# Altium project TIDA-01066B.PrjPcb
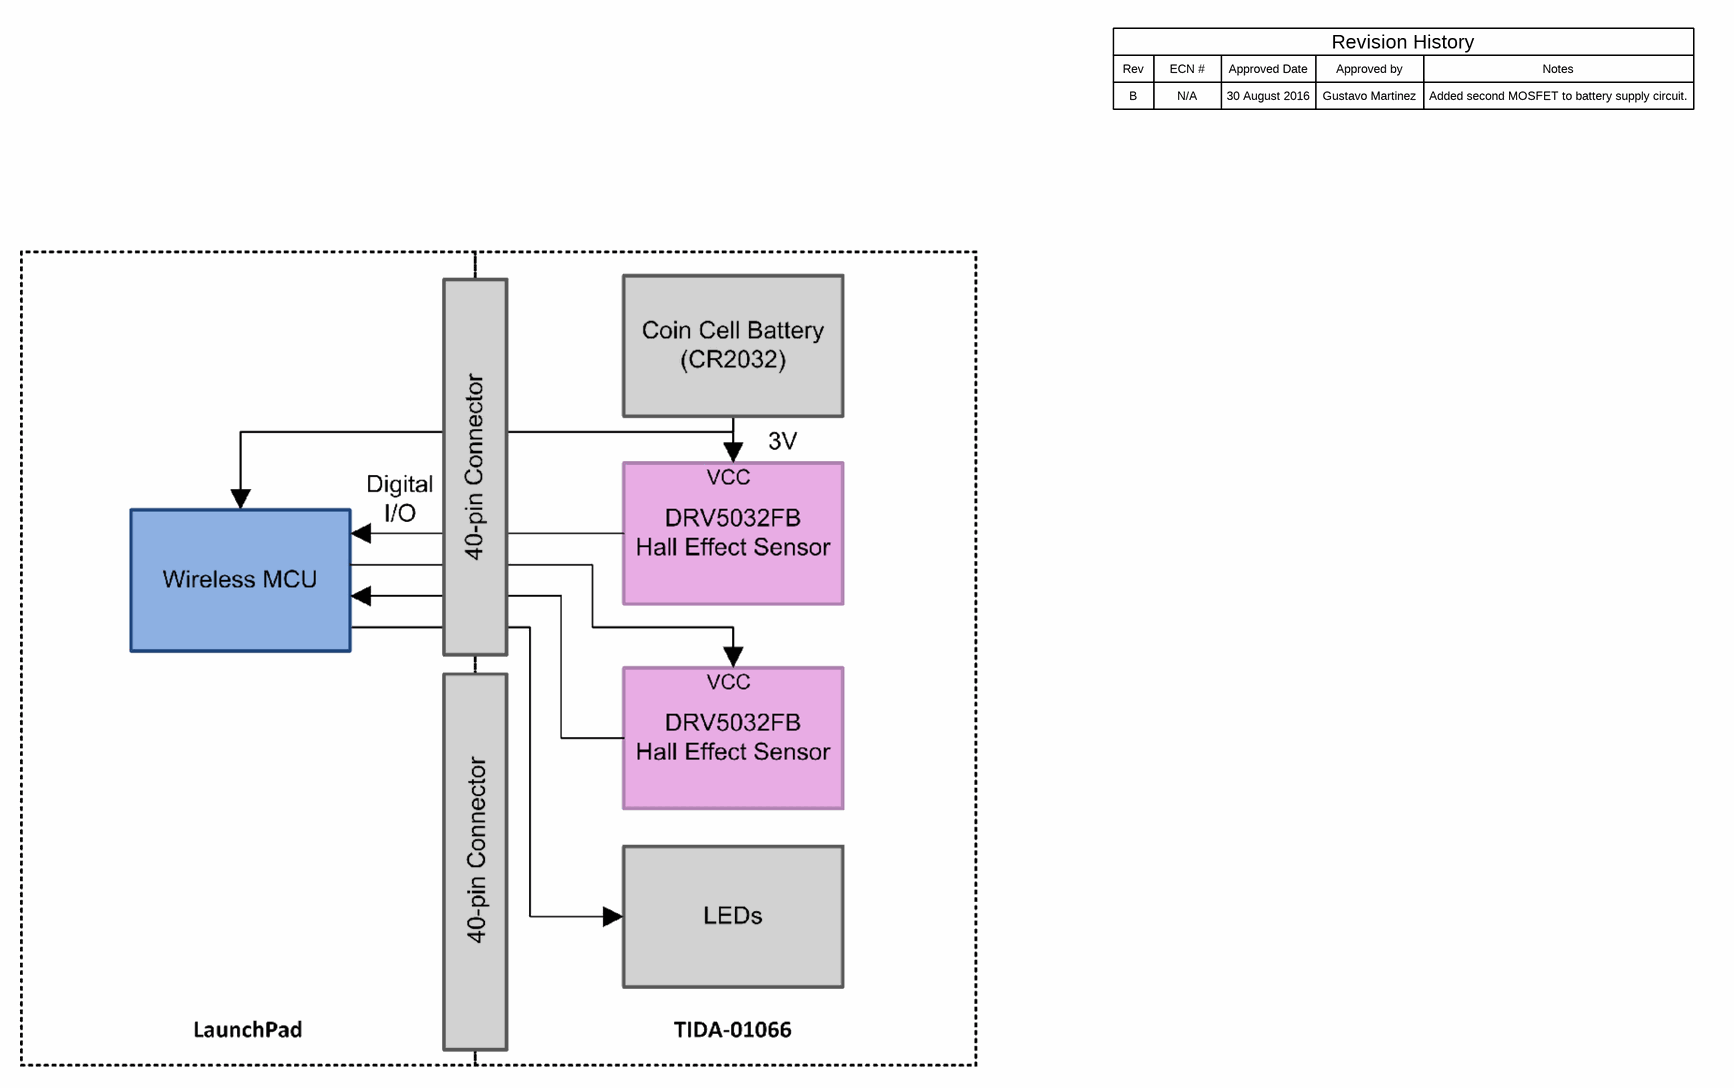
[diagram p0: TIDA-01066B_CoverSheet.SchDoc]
CopyrightYear: 2016; PCB_Layout: Krypton Solutions/RS; PCB_Rev: B; PRJ_Customer: Public Release; PRJ_Engineer: Gustavo Martinez; PRJ_Number: TIDA-01066; PRJ_Title: Low Power Window Contact Switch with Sub-1GHz; SCH_Rev: B; TechSupport: http://www.ti.com/support; TID: TIDA-01066
3 sheets, 44 parts. Net scope: global (net labels, ports and power ports of the same name join across sheets).
Board file: TIDA-01066B_PCB.PcbDoc
Sheets:
  TIDA-01066B_CoverSheet.SchDoc
  TIDA-01066B_Hall_Effect_Sensor.SchDoc
  TIDA-01066B_EVM_Hardware.SchDoc

## Sheet TIDA-01066B_CoverSheet.SchDoc: Cover Sheet
size 431 x 279 mm; Date: Not shown in title block; ApprovedBy: Not shown in title block; CheckedBy: Not shown in title block; Author: Not shown in title block; CompanyName: Not shown in title block; Engineer: Not shown in title block; Organization: Not shown in title block; Address1: Not shown in title block; Address2: Not shown in title block; Address3: Not shown in title block; Address4: Not shown in title block; DocumentNumber: 1; Revision: Use project parameter SCH_Rev; SheetNumber: 1; SheetTotal: 3; PageSetup: Record=PageOptions¦CenterHorizontal=True¦CenterVertical=True¦PrintScale=1.00¦XCorrection=1.00¦YCorrection=1.00¦PrintKind=0¦BorderSize=5000000¦LeftOffset=0¦BottomOffset=0¦Orientation=2¦PaperLength=1000¦PaperWidth=1000¦Scale=100¦PaperSource=15¦PrintQuality=600¦MediaType=1¦DitherType=10¦PaperKind=Letter¦PrintScaleMode=1

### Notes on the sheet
- Rev
- B
- ECN #
- N/A
- Approved Date
- 30 August 2016
- Approved by
- Gustavo Martinez
- Revision History
- Notes
- Added second MOSFET to battery supply circuit.

## Sheet TIDA-01066B_Hall_Effect_Sensor.SchDoc: Hall Effect Sensors
size 431 x 279 mm; Date: Not shown in title block; ApprovedBy: Not shown in title block; CheckedBy: Not shown in title block; Author: Not shown in title block; CompanyName: Not shown in title block; Engineer: Not shown in title block; Organization: Not shown in title block; Address1: Not shown in title block; Address2: Not shown in title block; Address3: Not shown in title block; Address4: Not shown in title block; DocumentNumber: 1; Revision: Use project parameter SCH_Rev; SheetNumber: 2; SheetTotal: 3; PageSetup: Record=PageOptions¦CenterHorizontal=True¦CenterVertical=True¦PrintScale=1.00¦XCorrection=1.00¦YCorrection=1.00¦PrintKind=0¦BorderSize=5000000¦LeftOffset=0¦BottomOffset=0¦Orientation=2¦PaperLength=1000¦PaperWidth=1000¦Scale=100¦PaperSource=15¦PrintQuality=600¦MediaType=1¦DitherType=10¦PaperKind=Letter¦PrintScaleMode=1
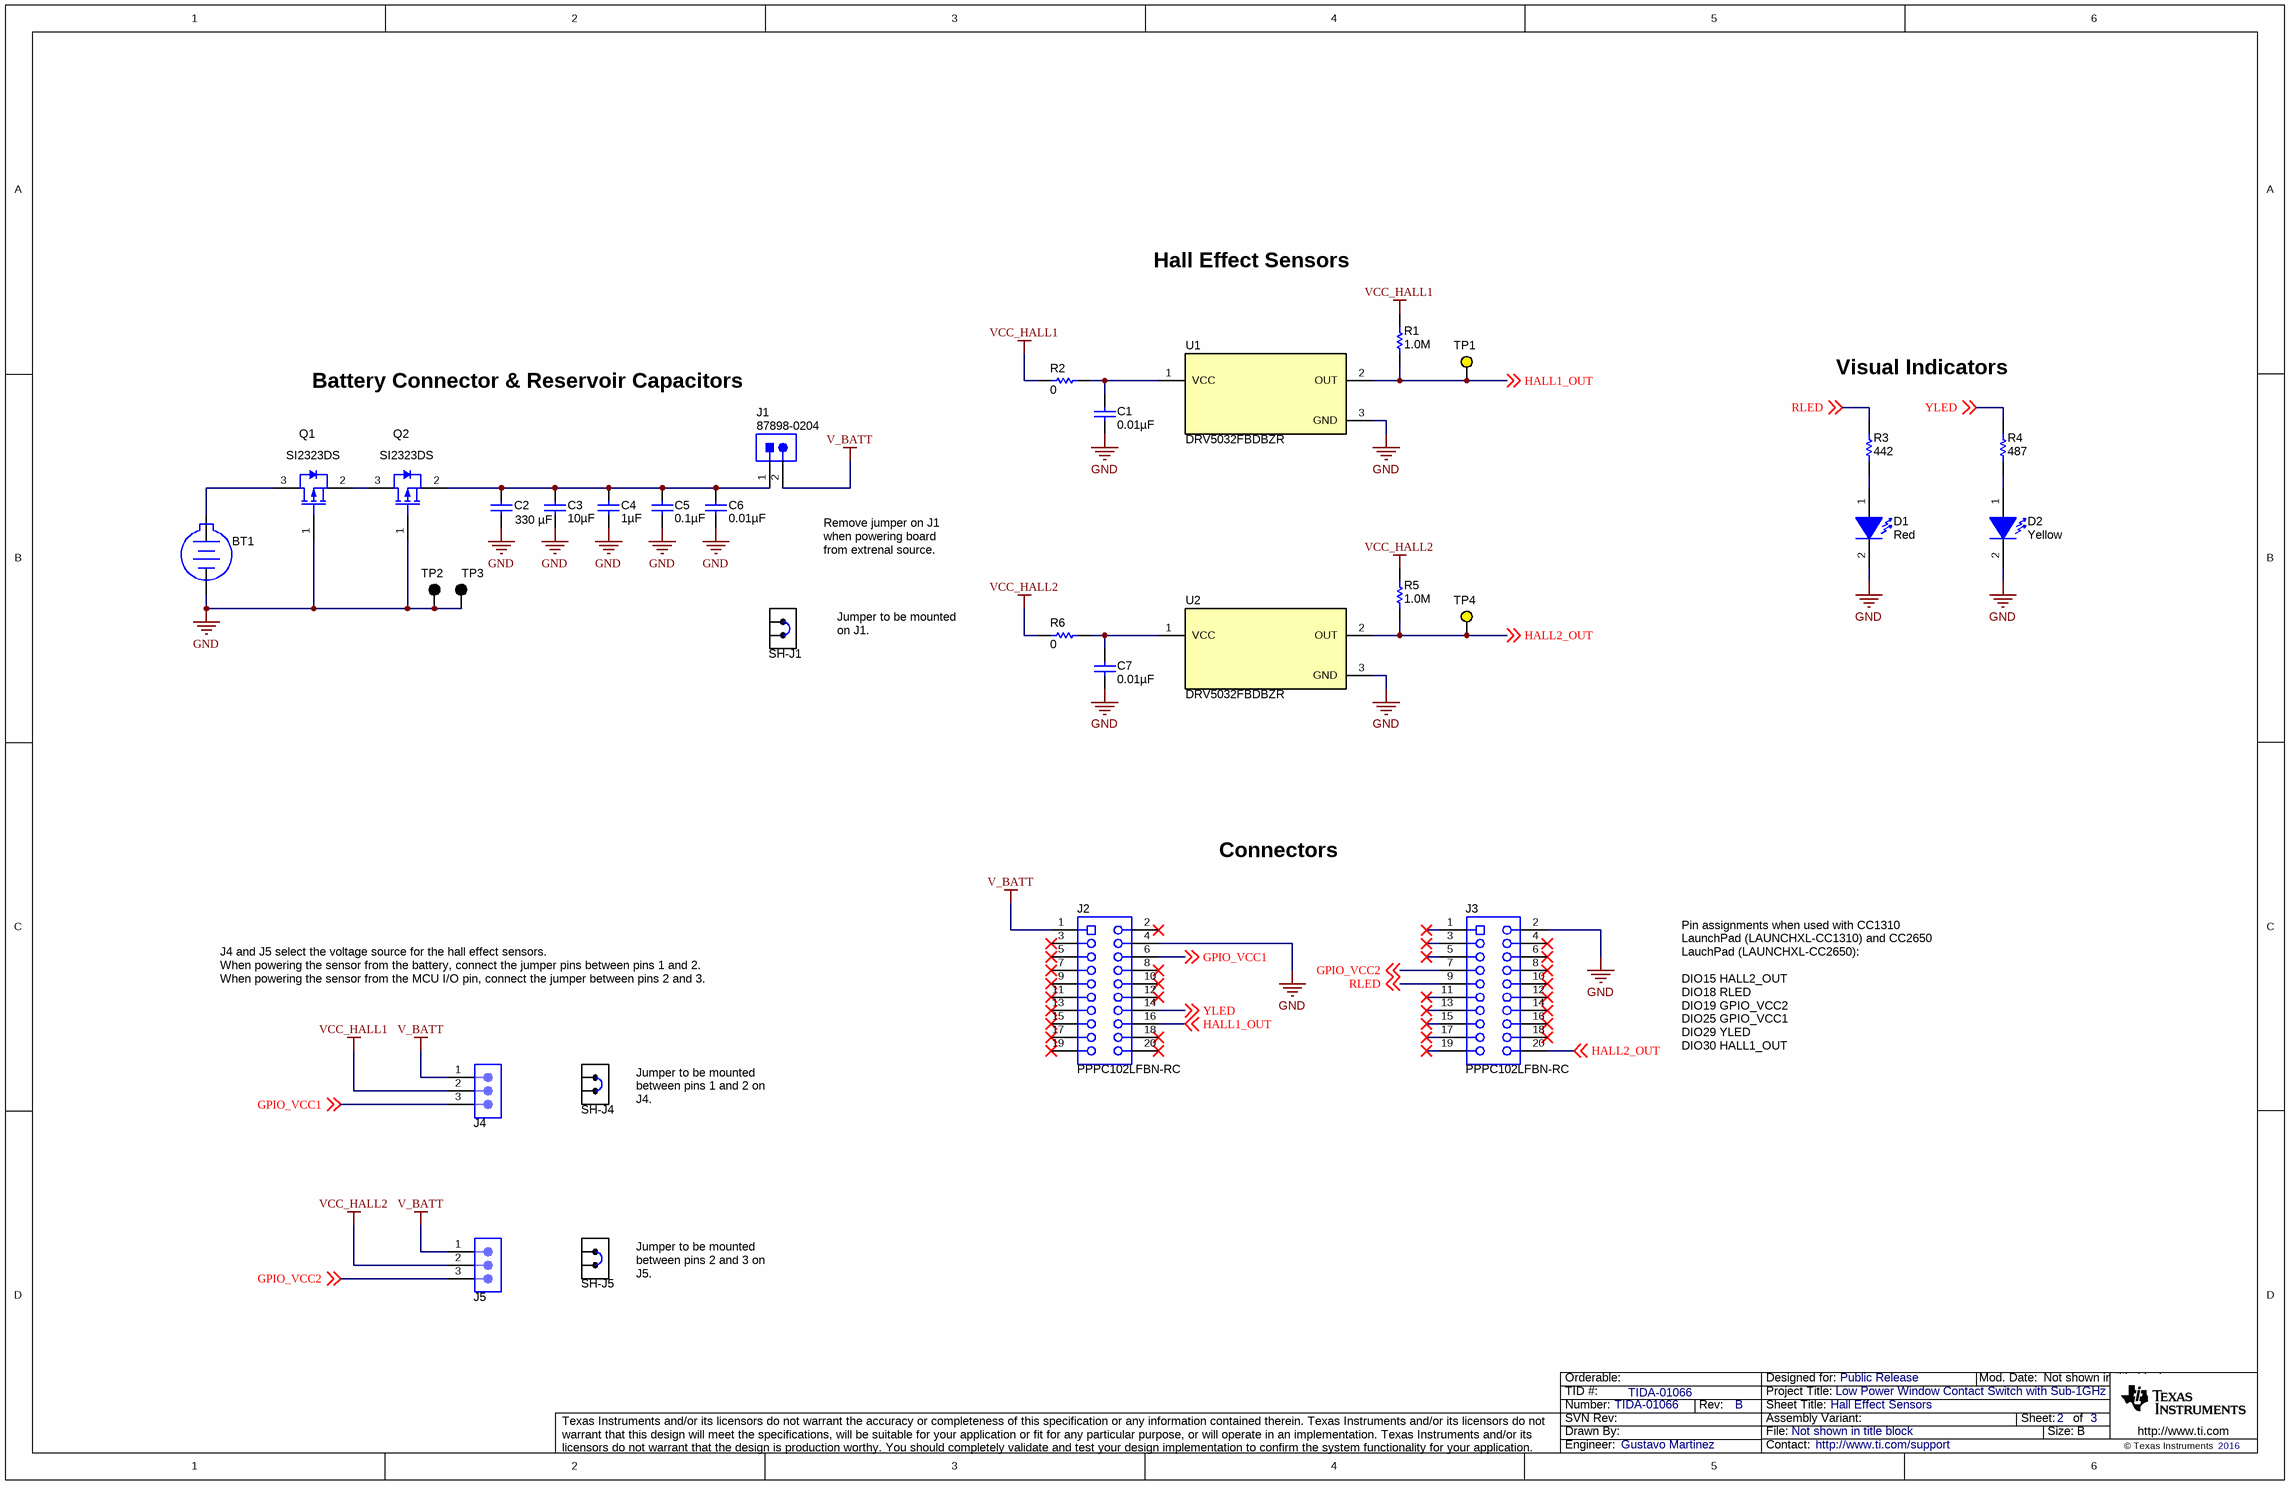
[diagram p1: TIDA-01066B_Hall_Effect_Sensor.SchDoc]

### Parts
BT1  BS-7  [BAT_BS-7]  (value not drawn)
C1  ValueDisplayed: 0.01µF  [0402]  (hidden comment: GRM155R71C103KA01D)
C2  ValueDisplayed: 330 µF  [1210]  (hidden comment: GRM32ER60G337ME05L)
C3  ValueDisplayed: 10µF  [0603]  (hidden comment: C1608X5R0J106M)
C4  ValueDisplayed: 1µF  [0603]  (hidden comment: C1608X7R1C105K)
C5  ValueDisplayed: 0.1µF  [0402]  (hidden comment: C1005X7R1H104K050BB)
C6  ValueDisplayed: 0.01µF  [0402]  (hidden comment: C1005X7R1C103K050BA)
C7  ValueDisplayed: 0.01µF  [0402]  (hidden comment: GRM155R71C103KA01D)
D1  value Red  [LS L29K_Red]  (hidden comment: LS L29K-G1J2-1-Z)
D2  value Yellow  [LY L29K_Yellow]  (hidden comment: LY L29K-H1K2-26-Z)
J1  87898-0204  [Molex_87898-0204]
J2  PPPC102LFBN-RC  [Sullins_PPPC102LFBN-RC]
J3  PPPC102LFBN-RC  [Sullins_PPPC102LFBN-RC]
J4  PBC03SAAN  [PBC03SAAN]  (value not drawn)
J5  PBC03SAAN  [PBC03SAAN]  (value not drawn)
Q1  SI2323DS  [SOT-23]
Q2  SI2323DS  [SOT-23]
R1  ValueDisplayed: 1.0M  [0805_HV]  (hidden comment: CRCW08051M00JNEA)
R2  ValueDisplayed: 0  [0805_HV]  (hidden comment: CRCW08050000Z0EA)
R3  ValueDisplayed: 442  [0805_HV]  (hidden comment: CRCW0805442RFKEA)
R4  ValueDisplayed: 487  [0805_HV]  (hidden comment: CRCW0805487RFKEA)
R5  ValueDisplayed: 1.0M  [0805_HV]  (hidden comment: CRCW08051M00JNEA)
R6  ValueDisplayed: 0  [0805_HV]  (hidden comment: CRCW08050000Z0EA)
SH-J1  969102-0000-DA  [SNT-100-BK-G]  (value not drawn)
SH-J4  969102-0000-DA  [SNT-100-BK-G]  (value not drawn)
SH-J5  969102-0000-DA  [SNT-100-BK-G]  (value not drawn)
TP1  5004  [Keystone5004]  (value not drawn)
TP2  5011  [Keystone5011]  (value not drawn)
TP3  5011  [Keystone5011]  (value not drawn)
TP4  5004  [Keystone5004]  (value not drawn)
U1  DRV5032FBDBZR  [DBZ0003A_N]
U2  DRV5032FBDBZR  [DBZ0003A_N]

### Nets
GND: BT1.2(-) C1.2 C2.2 C3.2 C4.2 C5.2 C6.2 C7.2 D1.2(K) D2.2(K) J2.4 J3.2 Q1.1(G) Q2.1(G) TP2.1 TP3.1 U1.3(GND) U2.3(GND)
V_BATT: J1.2 J2.1 J4.1 J5.1
VCC_HALL1: J4.2 R1.2 R2.1
VCC_HALL2: J5.2 R5.2 R6.1
GPIO_VCC1: J2.6 J4.3 ; off-sheet GPIO_VCC1
GPIO_VCC2: J3.7 J5.3 ; off-sheet GPIO_VCC2
HALL1_OUT: J2.16 R1.1 TP1.1 U1.2(OUT) ; off-sheet HALL1_OUT
HALL2_OUT: J3.20 R5.1 TP4.1 U2.2(OUT) ; off-sheet HALL2_OUT
RLED: J3.9 R3.2 ; off-sheet RLED
YLED: J2.14 R4.2 ; off-sheet YLED
NetBT1_1: BT1.1(+) Q1.3(D)
NetC1_1: C1.1 R2.2 U1.1(VCC)
NetC2_1: C2.1 C3.1 C4.1 C5.1 C6.1 J1.1 Q2.2(S)
NetC7_1: C7.1 R6.2 U2.1(VCC)
NetD1_1: D1.1(A) R3.1
NetD2_1: D2.1(A) R4.1
NetQ1_2: Q1.2(S) Q2.3(D)

Not connected (* = marked no-connect by the designer): J2 2* 3* 5* 7* 8* 9* 10* 11* 12* 13* 15* 17* 18* 19* 20*; J3 1* 3* 4* 5* 6* 8* 10* 11* 12* 13* 14* 15* 16* 17* 18* 19*

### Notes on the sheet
- Hall Effect Sensors
- Visual Indicators
- Battery Connector & Reservoir Capacitors
- Remove jumper on J1 when powering board from extrenal source.
- Jumper to be mounted on J1.
- Connectors
- J4 and J5 select the voltage source for the hall effect sensors.
  When powering the sensor from the battery, connect the jumper pins between pins 1 and 2.
  When powering the sensor from the MCU I/O pin, connect the jumper between pins 2 and 3.
- Pin assignments when used with CC1310 LaunchPad (LAUNCHXL-CC1310) and CC2650 LauchPad (LAUNCHXL-CC2650):
  DIO15	HALL2_OUT
  DIO18	RLED
  DIO19	GPIO_VCC2
  DIO25	GPIO_VCC1
  DIO29	YLED
  DIO30	HALL1_OUT
- (near SH-J4) Jumper to be mounted between pins 1 and 2 on J4.
- (near SH-J5) Jumper to be mounted between pins 2 and 3 on J5.

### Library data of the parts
BT1 = BS-7: Battery Holder, CR2032, Retainer clip, TH; Manufacturer: Memory Protection Devices; SymbolCreator: a0412235
C1 C7 = GRM155R71C103KA01D: CAP, CERM, 0.01 µF, 16 V, +/- 10%, X7R, 0402; Manufacturer: MuRata; Polarized: N; CompType: Capacitor; Value: 0.01uF; U/M: EA; Cap_F: 0.00000001; Tolerance_%: 10; Value1: Unknown; VDC_V: 16; Value2: 16V; TaMin_C: -55; TaMax_C: 125; SizeArea_mm2: 0.5; SizeAreaWB_mm2: 3; SizeX_mm: 1; SizeZ_mm: 0.6; AEC Category: Q200
C2 = Capacitor: CAP, CERM, 330 µF, 4 V, X5R, +/- 20%, 1210; Manufacturer: Murata; Polarized: N; Value: 330 uF; U/M: EA
C3 = C1608X5R0J106M: CAP, CERM, 10 µF, 6.3 V, +/- 20%, X5R, 0603; Manufacturer: TDK; Polarized: N; CompType: Capacitor; Value: 10uF; U/M: EA; Cap_F: 0.00001; Tolerance_%: 20; ESR_ohm: 0.005; Value1: 0.005 ohm; VDC_V: 6.3; Value2: 6.3V; IRMS_A: 1.9; TaMin_C: -25; TaMax_C: 85; AEC Category: Q200
C4 = C1608X7R1C105K: CAP, CERM, 1 µF, 16 V, +/- 10%, X7R, 0603; Manufacturer: TDK; Polarized: N; CompType: Capacitor; Value: 1uF; U/M: EA; Cap_F: 0.000001; Tolerance_%: 10; ESR_ohm: 0.0057; Value1: 0.0057 ohm; VDC_V: 16; Value2: 16V; TaMin_C: -55; TaMax_C: 125; AEC Category: Q200
C5 = C1005X7R1H104K050BB: CAP, CERM, 0.1 µF, 50 V, +/- 10%, X7R, 0402; Manufacturer: TDK; Polarized: N; CompType: Capacitor; Value: 0.1uF; U/M: EA; Cap_F: 0.0000001; Tolerance_%: 10; Value1: Unknown; VDC_V: 50; Value2: 50V; TaMin_C: -55; TaMax_C: 125; AEC Category: Q200
C6 = C1005X7R1C103K050BA: CAP, CERM, 0.01 µF, 16 V, +/- 10%, X7R, 0402; Manufacturer: TDK; Polarized: N; CompType: Capacitor; Value: 0.01uF; U/M: EA; Cap_F: 0.00000001; Tolerance_%: 10; ESR_ohm: 0.0623; Value1: 0.0623 ohm; VDC_V: 16; Value2: 16V; TaMin_C: -55; TaMax_C: 125; AEC Category: Q200
D1 = LS L29K-G1J2-1-Z: LED, Red, SMD; Manufacturer: OSRAM; Vf_V: 1.8; Value2: 1.8V; Io_A: 0.02; Vr_V: 12; Tjmax_C: 110; Value1: W; Angle: 160; U/M: EA
D2 = LY L29K-H1K2-26-Z: LED, Yellow, SMD; Manufacturer: OSRAM; Vf_V: 1.8; Value2: 1.8V; Io_A: 0.02; Vr_V: 12; Tjmax_C: 110; Value1: W; Angle: 160; U/M: EA
J1 = 87898-0204: Header, 2.54 mm, 2x1, Gold, R/A, SMT; Manufacturer: Molex; SymbolCreator: a0412235; U/M: EA
J2 J3 = PPPC102LFBN-RC: Receptacle, 100mil, 10x2, Gold, TH; Manufacturer: Sullins Connector Solutions; SymbolCreator: a0412235
J4 J5 = PBC03SAAN: Header, 100mil, 3x1, Gold, TH; Manufacturer: Sullins Connector Solutions
Q1 Q2 = SI2323DS: MOSFET, P-CH, -20 V, -3.7 A, SOT-23; Manufacturer: Vishay-Siliconix; Alternate Manufacturer: None; U/M: EA; ChType: P; Value: -20V; Value1: 0.031 ohm; Rdson45_ohm: 0.031; Value2: 12.5 nC; QgTyp_nC: 12.5; Vgs_V: -8; AEC Category: Q101
R1 R5 = CRCW08051M00JNEA: RES, 1.0 M, 5%, 0.125 W, 0805; Manufacturer: Vishay-Dale; CompType: Resistor; Value: 1.0Meg; Res_ohm: 1000000; Value_Code: 1M00; Tolerance_%: 5; Power_W: 0.125; Value2: 0.125W; VDC_V: 150; TempCo: 200 ppm/C; SizeArea_mm2: 2.5; SizeX_mm: 2; SizeY_mm: 1.25; SizeZ_mm: 1.45; EIA_Code: E24; U/M: EA; AEC Category: Q200
R2 R6 = CRCW08050000Z0EA: RES, 0, 5%, 0.125 W, 0805; Manufacturer: Vishay-Dale; CompType: Resistor; Value: 0; Value_Code: 0000; Tolerance_%: 5; Power_W: 0.125; Value2: 0.125W; VDC_V: 150; TempCo: 200 ppm/C; EIA_Code: E24; U/M: EA; AEC Category: Q200
R3 = CRCW0805442RFKEA: RES, 442, 1%, 0.125 W, 0805; Manufacturer: Vishay-Dale; CompType: Resistor; Value: 442; Value_Code: 442R; Tolerance_%: 1; Power_W: 0.125; Value2: 0.125W; VDC_V: 150; TempCo: 100 ppm/C; SizeArea_mm2: 2.5; SizeX_mm: 2; SizeY_mm: 1.25; SizeZ_mm: 1.45; EIA_Code: E96; U/M: EA; AEC Category: Q200
R4 = CRCW0805487RFKEA: RES, 487, 1%, 0.125 W, 0805; Manufacturer: Vishay-Dale; CompType: Resistor; Value: 487; Value_Code: 487R; Tolerance_%: 1; Power_W: 0.125; Value2: 0.125W; VDC_V: 150; TempCo: 100 ppm/C; SizeArea_mm2: 2.5; SizeX_mm: 2; SizeY_mm: 1.25; SizeZ_mm: 1.45; EIA_Code: E96; U/M: EA; AEC Category: Q200
SH-J1 SH-J4 SH-J5 = 969102-0000-DA: Shunt, 100mil, Gold plated, Black; Manufacturer: 3M; Alternate Manufacturer: Samtec; Value: 1x2; Note: You can "mate" this to a header by matching the designator.  i.e. use SH-J3 for header J3
TP1 TP4 = 5004: Test Point, Miniature, Yellow, TH; Manufacturer: Keystone; CompType: Test Point Loop; ContactFinish: Silver
TP2 TP3 = 5011: Test Point, Multipurpose, Black, TH; Manufacturer: Keystone; CompType: Test Point Loop; ContactFinish: Silver
U1 U2 = DRV5032FBDBZR: Ultra-Low Power Digital-Switch Hall Effect Sensor, DBZ0003A; Manufacturer: Texas Instruments; SymbolCreator: Altium; SizeArea_mm2: 7.5; SizeAreaWB_mm2: 14; SizeX_mm: 2.5; SizeY_mm: 3; SizeZ_mm: 1.12; CompType: IC; U/M: EA

## Sheet TIDA-01066B_EVM_Hardware.SchDoc: EVM Hardware
size 431 x 279 mm; Date: Not shown in title block; ApprovedBy: Not shown in title block; CheckedBy: Not shown in title block; Author: Not shown in title block; CompanyName: Not shown in title block; Engineer: Not shown in title block; Organization: Not shown in title block; Address1: Not shown in title block; Address2: Not shown in title block; Address3: Not shown in title block; Address4: Not shown in title block; DocumentNumber: 1; Revision: Use project parameter SCH_Rev; SheetNumber: 3; SheetTotal: 3; PageSetup: Record=PageOptions¦CenterHorizontal=True¦CenterVertical=True¦PrintScale=1.00¦XCorrection=1.00¦YCorrection=1.00¦PrintKind=0¦BorderSize=5000000¦LeftOffset=0¦BottomOffset=0¦Orientation=2¦PaperLength=1000¦PaperWidth=1000¦Scale=100¦PaperSource=15¦PrintQuality=600¦MediaType=1¦DitherType=10¦PaperKind=Letter¦PrintScaleMode=1
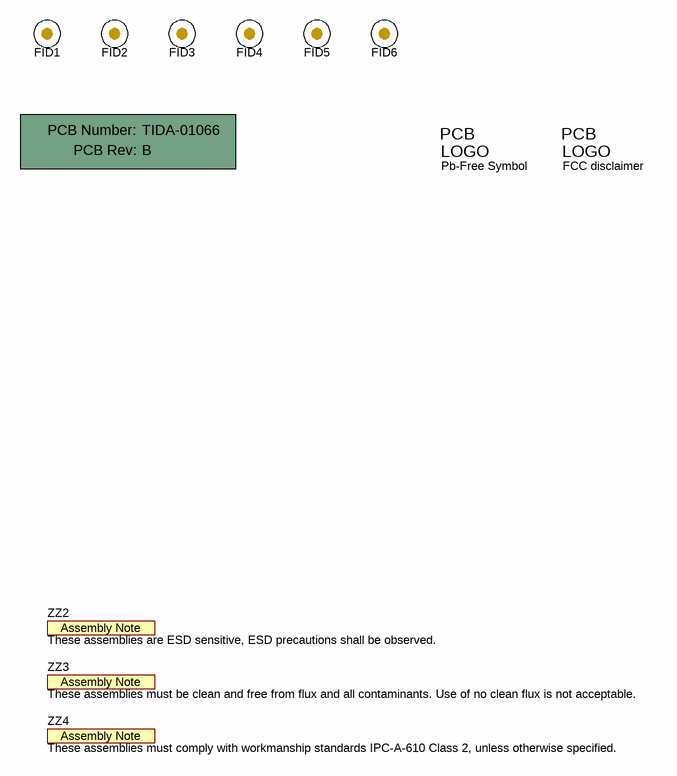
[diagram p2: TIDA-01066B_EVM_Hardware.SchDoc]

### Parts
!PCB1  Printed Circuit Board  (value not drawn)  (mechanical)
FID1  Fiducial  [Fiducial10-20]  (value not drawn)
FID2  Fiducial  [Fiducial10-20]  (value not drawn)
FID3  Fiducial  [Fiducial10-20]  (value not drawn)
FID4  Fiducial  [Fiducial10-20]  (value not drawn)
FID5  Fiducial  [Fiducial10-20]  (value not drawn)
FID6  Fiducial  [Fiducial10-20]  (value not drawn)
Logo2  Pb-Free Symbol  [Pb-Free_Overlay_Small]  (no BOM)
Logo3  FCC disclaimer  [FCC_disclaimer]  (no BOM)
ZZ2  These assemblies are ESD sensitive, ESD precautions shall be observed.  [AssemblyNote]  (no BOM)
ZZ3  These assemblies must be clean and free from flux and all contaminants. Use of no clean flux is not acceptable.  [AssemblyNote]  (no BOM)
ZZ4  These assemblies must comply with workmanship standards IPC-A-610 Class 2, unless otherwise specified.  [AssemblyNote]  (no BOM)

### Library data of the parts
!PCB1 = PCB: Manufacturer: Any; PartNumber: TIDA-01066; SymbolCreator: a0412235
FID1-FID6 = Fiducial: Fiducial mark.  There is nothing to buy or mount.; SymbolCreator: codlsc
Logo2 = Pb-Free: SymbolCreator: a0412235
Logo3 = FCC_disclaimer: SymbolCreator: codlsc
ZZ2-ZZ4 = AssemblyNote: SymbolCreator: codlsc

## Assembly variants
001: not fitted FID1 FID2 FID3 R1 R5 TP1 TP4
